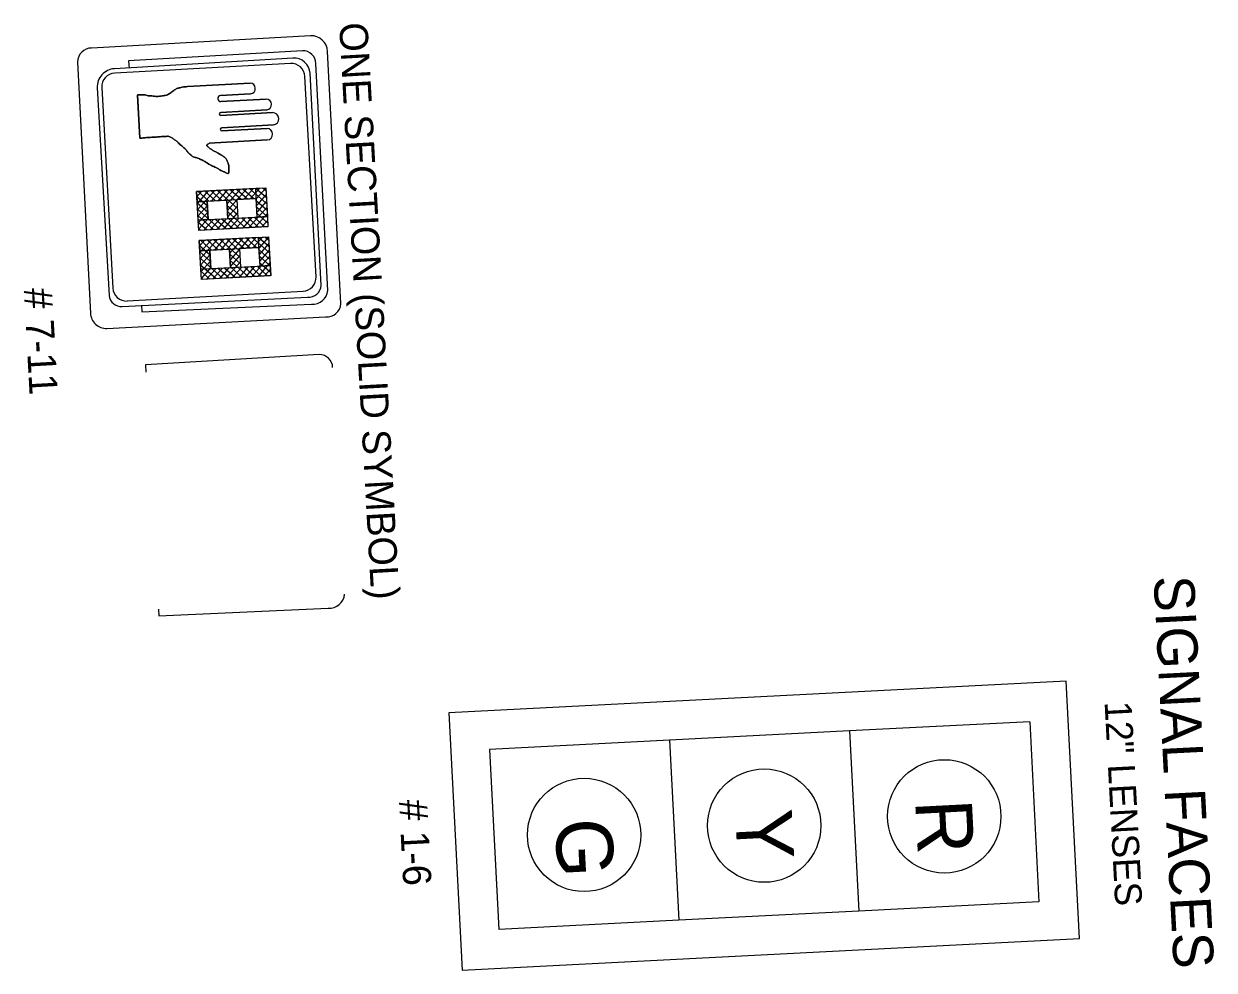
# Model space of a CAD drawing. Extents: x -218554 to 420030, y -566264 to -483460.
# Drawn here: x -218285.8 to -218207.2, y -484168.8 to -484106.3 of the extents above; entities that cross this region are included whole.
import ezdxf

# ---------------------------------------------------------------- set-up
doc = ezdxf.new("R2010")
doc.units = 0
for name, color, linetype in [('G-ANNO-STMP', 7, 'Continuous'), ('Level 1', 7, 'Continuous'), ('Level 61', 7, 'Continuous')]:
    doc.layers.add(name, color=color, linetype=linetype)

msp = doc.modelspace()

# ---------------------------------------------------------------- linework, layer by layer
at = {"layer": 'Level 1'}
for p, q in [((-218266.858, -484107.089), (-218281.297, -484107.896)), ((-218264.85, -484124.763), (-218265.721, -484108.12)), ((-218282.226, -484108.821), (-218281.371, -484125.397)), ((-218268.029, -484108.558), (-218279.793, -484109.264)), ((-218265.704, -484123.89), (-218266.495, -484108.923)), ((-218266.149, -484123.569), (-218266.874, -484109.566)), ((-218280.924, -484110.527), (-218280.144, -484124.236)), ((-218274.981, -484110.441), (-218270.845, -484110.213)), ((-218270.845, -484110.213), (-218274.981, -484110.441)), ((-218278.123, -484113.841), (-218278.279, -484111.01)), ((-218278.264, -484110.994), (-218278.124, -484113.853)), ((-218270.814, -484110.923), (-218272.786, -484111.031)), ((-218272.786, -484111.031), (-218270.814, -484110.923)), ((-218272.764, -484111.431), (-218269.772, -484111.266)), ((-218269.772, -484111.266), (-218272.764, -484111.431)), ((-218272.779, -484112.349), (-218269.354, -484112.16)), ((-218269.354, -484112.16), (-218272.779, -484112.349)), ((-218269.741, -484111.977), (-218272.775, -484112.144)), ((-218272.775, -484112.144), (-218269.741, -484111.977)), ((-218272.707, -484113.367), (-218269.722, -484113.203)), ((-218269.722, -484113.203), (-218272.707, -484113.367)), ((-218269.301, -484112.975), (-218272.702, -484113.162)), ((-218272.702, -484113.162), (-218269.301, -484112.975)), ((-218278.126, -484113.855), (-218278.123, -484113.841)), ((-218269.705, -484113.964), (-218273.547, -484114.175)), ((-218273.547, -484114.175), (-218269.705, -484113.964)), ((-218271.049, -484117.19), (-218272.344, -484118.636)), ((-218270.624, -484117.167), (-218271.253, -484117.869)), ((-218270.863, -484117.18), (-218269.742, -484118.184)), ((-218270.2, -484117.144), (-218270.829, -484117.846)), ((-218270.438, -484117.157), (-218269.766, -484117.759)), ((-218269.799, -484117.147), (-218270.428, -484117.85)), ((-218270.014, -484117.133), (-218269.789, -484117.335)), ((-218274.355, -484117.686), (-218273.652, -484118.315)), ((-218274.021, -484117.354), (-218274.352, -484117.724)), ((-218273.596, -484117.331), (-218274.329, -484118.149)), ((-218273.172, -484117.307), (-218274.306, -484118.573)), ((-218274.259, -484117.367), (-218273.557, -484117.996)), ((-218273.835, -484117.344), (-218273.133, -484117.973)), ((-218273.41, -484117.32), (-218272.708, -484117.949)), ((-218272.747, -484117.284), (-218273.376, -484117.986)), ((-218272.986, -484117.297), (-218271.686, -484118.462)), ((-218272.323, -484117.261), (-218272.952, -484117.963)), ((-218272.561, -484117.274), (-218271.709, -484118.037)), ((-218271.898, -484117.237), (-218272.527, -484117.94)), ((-218272.382, -484117.932), (-218272.315, -484119.162)), ((-218271.473, -484117.214), (-218272.367, -484118.212)), ((-218272.137, -484117.25), (-218271.434, -484117.879)), ((-218271.717, -484117.895), (-218271.649, -484119.125)), ((-218271.712, -484117.227), (-218271.01, -484117.856)), ((-218271.287, -484117.204), (-218270.585, -484117.833)), ((-218270.421, -484117.979), (-218269.719, -484118.608)), ((-218269.776, -484117.572), (-218270.405, -484118.274)), ((-218274.331, -484118.11), (-218273.629, -484118.739)), ((-218274.308, -484118.535), (-218272.831, -484119.858)), ((-218273.653, -484118.296), (-218274.282, -484118.998)), ((-218273.63, -484118.72), (-218274.259, -484119.423)), ((-218272.365, -484118.257), (-218271.662, -484118.886)), ((-218272.341, -484118.682), (-218271.132, -484119.764)), ((-218271.691, -484118.358), (-218272.32, -484119.061)), ((-218269.729, -484118.421), (-218270.922, -484119.752)), ((-218270.398, -484118.404), (-218269.696, -484119.033)), ((-218269.753, -484117.996), (-218270.382, -484118.699)), ((-218274.284, -484118.959), (-218273.255, -484119.881)), ((-218274.261, -484119.384), (-218273.68, -484119.904)), ((-218273.606, -484119.145), (-218274.235, -484119.847)), ((-218273.265, -484119.214), (-218273.894, -484119.916)), ((-218272.84, -484119.19), (-218273.469, -484119.893)), ((-218273.109, -484119.205), (-218272.406, -484119.834)), ((-218272.416, -484119.167), (-218273.045, -484119.869)), ((-218272.684, -484119.182), (-218271.982, -484119.811)), ((-218271.668, -484118.783), (-218272.62, -484119.846)), ((-218272.318, -484119.106), (-218271.557, -484119.787)), ((-218271.566, -484119.12), (-218272.195, -484119.823)), ((-218271.142, -484119.097), (-218271.771, -484119.799)), ((-218271.41, -484119.112), (-218270.708, -484119.741)), ((-218270.717, -484119.074), (-218271.346, -484119.776)), ((-218270.986, -484119.088), (-218270.283, -484119.717)), ((-218270.561, -484119.065), (-218269.859, -484119.694)), ((-218269.706, -484118.846), (-218270.497, -484119.729)), ((-218270.375, -484118.828), (-218269.672, -484119.457)), ((-218269.683, -484119.27), (-218270.073, -484119.706)), ((-218274.238, -484119.809), (-218274.104, -484119.928)), ((-218274.176, -484120.923), (-218273.474, -484121.552)), ((-218273.843, -484120.591), (-218274.174, -484120.962)), ((-218273.418, -484120.568), (-218274.151, -484121.386)), ((-218272.993, -484120.545), (-218274.127, -484121.811)), ((-218274.081, -484120.605), (-218273.379, -484121.234)), ((-218273.657, -484120.581), (-218272.954, -484121.21)), ((-218273.232, -484120.558), (-218272.53, -484121.187)), ((-218272.569, -484120.521), (-218273.198, -484121.224)), ((-218272.807, -484120.534), (-218271.507, -484121.699)), ((-218272.144, -484120.498), (-218272.773, -484121.2)), ((-218272.383, -484120.511), (-218271.531, -484121.274)), ((-218271.72, -484120.475), (-218272.349, -484121.177)), ((-218271.295, -484120.451), (-218272.189, -484121.449)), ((-218270.871, -484120.428), (-218272.165, -484121.873)), ((-218271.958, -484120.488), (-218271.256, -484121.117)), ((-218271.534, -484120.464), (-218270.831, -484121.093)), ((-218271.109, -484120.441), (-218270.407, -484121.07)), ((-218270.446, -484120.404), (-218271.075, -484121.107)), ((-218270.685, -484120.418), (-218269.564, -484121.421)), ((-218270.022, -484120.381), (-218270.651, -484121.083)), ((-218270.26, -484120.394), (-218269.587, -484120.997)), ((-218269.621, -484120.385), (-218270.25, -484121.087)), ((-218269.598, -484120.809), (-218270.227, -484121.511)), ((-218269.835, -484120.371), (-218269.611, -484120.572)), ((-218274.153, -484121.348), (-218273.451, -484121.977)), ((-218274.129, -484121.772), (-218272.652, -484123.095)), ((-218273.475, -484121.533), (-218274.104, -484122.235)), ((-218272.204, -484121.169), (-218272.136, -484122.399)), ((-218272.186, -484121.494), (-218271.484, -484122.123)), ((-218271.513, -484121.596), (-218272.142, -484122.298)), ((-218271.538, -484121.132), (-218271.471, -484122.362)), ((-218269.551, -484121.658), (-218270.743, -484122.99)), ((-218270.243, -484121.217), (-218269.541, -484121.846)), ((-218270.22, -484121.641), (-218269.517, -484122.27)), ((-218269.574, -484121.234), (-218270.203, -484121.936)), ((-218274.106, -484122.197), (-218273.077, -484123.118)), ((-218274.083, -484122.621), (-218273.502, -484123.142)), ((-218273.452, -484121.958), (-218274.081, -484122.66)), ((-218273.428, -484122.382), (-218274.057, -484123.084)), ((-218273.086, -484122.451), (-218273.715, -484123.153)), ((-218272.662, -484122.428), (-218273.291, -484123.13)), ((-218272.93, -484122.443), (-218272.228, -484123.072)), ((-218272.237, -484122.404), (-218272.866, -484123.107)), ((-218272.506, -484122.419), (-218271.803, -484123.048)), ((-218271.49, -484122.02), (-218272.442, -484123.083)), ((-218272.163, -484121.919), (-218270.954, -484123.001)), ((-218272.139, -484122.343), (-218271.379, -484123.025)), ((-218271.388, -484122.358), (-218272.017, -484123.06)), ((-218270.964, -484122.334), (-218271.593, -484123.037)), ((-218271.232, -484122.349), (-218270.53, -484122.978)), ((-218270.539, -484122.311), (-218271.168, -484123.013)), ((-218270.807, -484122.326), (-218270.105, -484122.955)), ((-218270.383, -484122.302), (-218269.681, -484122.931)), ((-218269.528, -484122.083), (-218270.319, -484122.966)), ((-218270.196, -484122.066), (-218269.494, -484122.695)), ((-218269.504, -484122.507), (-218269.894, -484122.943)), ((-218274.059, -484123.046), (-218273.926, -484123.165)), ((-218279.286, -484124.948), (-218267.051, -484124.332)), ((-218280.29, -484126.408), (-218265.861, -484125.648))]:
    msp.add_line(p, q, dxfattribs=at)
for points in [[(-218267.382, -484108.074), (-218278.854, -484108.74), (-218278.828, -484109.222)], [(-218268.174, -484108.914), (-218279.777, -484109.553)], [(-218266.488, -484122.997), (-218267.216, -484109.772)], [(-218280.635, -484110.511), (-218279.907, -484123.736)], [(-218272.315, -484119.162), (-218273.602, -484119.232), (-218273.669, -484118.002), (-218272.382, -484117.932)], [(-218271.649, -484119.125), (-218270.362, -484119.054), (-218270.43, -484117.824), (-218271.717, -484117.895)], [(-218271.471, -484122.362), (-218270.184, -484122.291), (-218270.252, -484121.061), (-218271.538, -484121.132)], [(-218272.136, -484122.399), (-218273.423, -484122.47), (-218273.491, -484121.24), (-218272.204, -484121.169)], [(-218278.949, -484124.593), (-218267.345, -484123.954)], [(-218277.999, -484124.874), (-218277.975, -484125.308), (-218266.795, -484124.802)], [(-218266.278, -484128.135), (-218277.749, -484128.801), (-218277.723, -484129.283)], [(-218276.895, -484144.935), (-218276.87, -484145.369), (-218265.69, -484144.863)]]:
    msp.add_lwpolyline(points, dxfattribs=at)
for points in [[(-218269.801, -484117.122), (-218269.66, -484119.683), (-218274.231, -484119.935), (-218274.372, -484117.373)], [(-218274.372, -484117.373), (-218274.337, -484118.029), (-218270.43, -484117.824), (-218270.464, -484117.169)], [(-218269.801, -484117.122), (-218269.701, -484119.019), (-218270.362, -484119.054), (-218270.461, -484117.156)], [(-218271.717, -484117.895), (-218271.652, -484119.127), (-218272.315, -484119.162), (-218272.379, -484117.93)], [(-218273.669, -484118.002), (-218273.605, -484119.224), (-218274.266, -484119.258), (-218274.33, -484118.037)], [(-218269.701, -484119.019), (-218269.666, -484119.696), (-218274.231, -484119.935), (-218274.266, -484119.258)], [(-218269.623, -484120.359), (-218269.481, -484122.92), (-218274.052, -484123.172), (-218274.193, -484120.611)], [(-218274.193, -484120.611), (-218274.159, -484121.266), (-218270.252, -484121.061), (-218270.286, -484120.406)], [(-218269.623, -484120.359), (-218269.523, -484122.257), (-218270.184, -484122.291), (-218270.283, -484120.394)], [(-218273.491, -484121.24), (-218273.427, -484122.461), (-218274.088, -484122.496), (-218274.152, -484121.274)], [(-218271.538, -484121.132), (-218271.474, -484122.364), (-218272.136, -484122.399), (-218272.201, -484121.167)], [(-218269.523, -484122.257), (-218269.488, -484122.933), (-218274.052, -484123.172), (-218274.088, -484122.496)]]:
    msp.add_lwpolyline(points, close=True, dxfattribs=at)
for centre, radius, start, end in [((-218266.806, -484108.173), 1.086, 2.77432, 92.77432), ((-218281.298, -484108.823), 0.927, 89.93321, 179.93321), ((-218267.363, -484108.942), 0.869, 1.27514, 91.27514), ((-218279.727, -484110.461), 1.198, 93.15216, 183.15216), ((-218268.124, -484109.822), 0.909, 3.15216, 93.15216), ((-218267.955, -484109.639), 1.083, 3.88192, 93.88192), ((-218279.727, -484110.461), 0.909, 93.15216, 183.15216), ((-218270.85, -484110.568), 0.356, 275.81971, 89.16653), ((-218270.85, -484110.568), 0.356, 275.81971, 89.16653), ((-218272.776, -484111.231), 0.2, 93.15216, 273.15216), ((-218272.776, -484111.231), 0.2, 93.15216, 273.15216), ((-218269.777, -484111.622), 0.356, 275.81971, 89.16653), ((-218269.777, -484111.622), 0.356, 275.81971, 89.16653), ((-218272.777, -484112.246), 0.102, 88.57477, 268.57477), ((-218272.777, -484112.246), 0.102, 88.57477, 268.57477), ((-218269.351, -484112.569), 0.409, 277.05213, 90.39894), ((-218269.351, -484112.569), 0.409, 277.05213, 90.39894), ((-218272.704, -484113.263), 0.104, 88.04746, 268.04746), ((-218272.704, -484113.263), 0.104, 88.04746, 268.04746), ((-218269.736, -484113.584), 0.381, 274.62974, 87.97656), ((-218269.736, -484113.584), 0.381, 274.62974, 87.97656), ((-218267.396, -484123.047), 0.909, 273.15216, 3.15216), ((-218279.359, -484124.163), 0.788, 185.26181, 275.26181), ((-218278.999, -484123.686), 0.909, 183.15216, 273.15216), ((-218266.982, -484123.499), 0.836, 265.22621, 355.22621), ((-218266.706, -484123.8), 1.005, 264.91062, 354.91062), ((-218265.798, -484124.7), 0.95, 266.18024, 356.18024), ((-218280.324, -484125.362), 1.047, 181.91264, 271.91264), ((-218266.259, -484129.003), 0.869, 1.27514, 91.27514), ((-218265.601, -484143.861), 1.005, 264.91062, 354.91062)]:
    msp.add_arc(centre, radius, start, end, dxfattribs=at)
for points in [[(-218278.264, -484110.994), (-218278.107, -484110.985), (-218277.841, -484110.981), (-218277.562, -484111.044), (-218277.246, -484111.066), (-218277.068, -484111.086), (-218276.724, -484111.067), (-218276.441, -484111.022), (-218276.296, -484110.984), (-218276.057, -484110.823), (-218275.821, -484110.653), (-218275.62, -484110.553), (-218275.406, -484110.502), (-218275.241, -484110.464), (-218275.134, -484110.458), (-218274.981, -484110.441)], [(-218274.981, -484110.441), (-218275.134, -484110.458), (-218275.241, -484110.464), (-218275.406, -484110.502), (-218275.62, -484110.553), (-218275.821, -484110.653), (-218276.057, -484110.823), (-218276.296, -484110.984), (-218276.441, -484111.022), (-218276.724, -484111.067), (-218277.068, -484111.086), (-218277.246, -484111.066), (-218277.562, -484111.044), (-218277.841, -484110.981), (-218278.107, -484110.985), (-218278.264, -484110.994)], [(-218273.546, -484114.173), (-218273.55, -484114.202), (-218273.627, -484114.245), (-218273.684, -484114.297), (-218273.691, -484114.327), (-218273.68, -484114.376), (-218273.638, -484114.403), (-218273.535, -484114.487), (-218273.453, -484114.55), (-218273.392, -484114.586), (-218273.341, -484114.623), (-218273.249, -484114.688), (-218273.168, -484114.721), (-218273.057, -484114.775), (-218272.996, -484114.81), (-218272.884, -484114.873), (-218272.781, -484114.946), (-218272.68, -484115), (-218272.578, -484115.063), (-218272.506, -484115.118), (-218272.423, -484115.202), (-218272.377, -484115.308), (-218272.344, -484115.365), (-218272.311, -484115.452), (-218272.277, -484115.528), (-218272.25, -484115.646), (-218272.245, -484115.744), (-218272.238, -484115.871), (-218272.241, -484115.989), (-218272.253, -484116.127), (-218272.271, -484116.168), (-218272.299, -484116.179), (-218272.43, -484116.127), (-218272.501, -484116.092), (-218272.573, -484116.057), (-218272.653, -484116.022), (-218272.703, -484116.005), (-218272.835, -484115.933), (-218273.019, -484115.825), (-218273.312, -484115.683), (-218273.646, -484115.505), (-218273.881, -484115.361), (-218274.033, -484115.28), (-218274.174, -484115.21), (-218274.287, -484115.171), (-218274.344, -484115.15), (-218274.586, -484115.076), (-218274.76, -484114.947), (-218274.884, -484114.846), (-218275.01, -484114.695), (-218275.085, -484114.601), (-218275.354, -484114.36), (-218275.581, -484114.146), (-218275.737, -484114.007), (-218275.91, -484113.889), (-218275.987, -484113.83), (-218276.095, -484113.781), (-218276.195, -484113.728), (-218276.412, -484113.74), (-218276.606, -484113.74), (-218276.783, -484113.75), (-218277.018, -484113.773), (-218277.244, -484113.786), (-218277.607, -484113.806), (-218277.9, -484113.831), (-218278.007, -484113.846), (-218278.086, -484113.851), (-218278.124, -484113.853)], [(-218278.124, -484113.853), (-218278.086, -484113.851), (-218278.007, -484113.846), (-218277.9, -484113.831), (-218277.607, -484113.806), (-218277.244, -484113.786), (-218277.018, -484113.773), (-218276.783, -484113.75), (-218276.606, -484113.74), (-218276.412, -484113.74), (-218276.195, -484113.728), (-218276.095, -484113.781), (-218275.987, -484113.83), (-218275.91, -484113.889), (-218275.737, -484114.007), (-218275.581, -484114.146), (-218275.354, -484114.36), (-218275.085, -484114.601), (-218275.01, -484114.695), (-218274.884, -484114.846), (-218274.76, -484114.947), (-218274.586, -484115.076), (-218274.344, -484115.15), (-218274.287, -484115.171), (-218274.174, -484115.21), (-218274.033, -484115.28), (-218273.881, -484115.361), (-218273.646, -484115.505), (-218273.312, -484115.683), (-218273.019, -484115.825), (-218272.835, -484115.933), (-218272.703, -484116.005), (-218272.653, -484116.022), (-218272.573, -484116.057), (-218272.501, -484116.092), (-218272.43, -484116.127), (-218272.299, -484116.179), (-218272.271, -484116.168), (-218272.253, -484116.127), (-218272.241, -484115.989), (-218272.238, -484115.871), (-218272.245, -484115.744), (-218272.25, -484115.646), (-218272.277, -484115.528), (-218272.311, -484115.452), (-218272.344, -484115.365), (-218272.377, -484115.308), (-218272.423, -484115.202), (-218272.506, -484115.118), (-218272.578, -484115.063), (-218272.68, -484115), (-218272.781, -484114.946), (-218272.884, -484114.873), (-218272.996, -484114.81), (-218273.057, -484114.775), (-218273.168, -484114.721), (-218273.249, -484114.688), (-218273.341, -484114.623), (-218273.392, -484114.586), (-218273.453, -484114.55), (-218273.535, -484114.487), (-218273.638, -484114.403), (-218273.68, -484114.376), (-218273.691, -484114.327), (-218273.684, -484114.297), (-218273.627, -484114.245), (-218273.55, -484114.202), (-218273.546, -484114.173)]]:
    msp.add_spline(points, degree=3, dxfattribs=at)
at = {"layer": 'Level 61'}
for p, q in [((-218219.388, -484152.359), (-218231.273, -484152.972)), ((-218219.388, -484152.359), (-218218.775, -484164.243)), ((-218231.273, -484152.972), (-218243.158, -484153.585)), ((-218231.273, -484152.972), (-218230.66, -484164.857)), ((-218243.158, -484153.585), (-218255.043, -484154.198)), ((-218243.158, -484153.585), (-218242.545, -484165.47)), ((-218255.043, -484154.198), (-218254.43, -484166.083)), ((-218218.775, -484164.243), (-218230.66, -484164.857)), ((-218230.66, -484164.857), (-218242.545, -484165.47)), ((-218242.545, -484165.47), (-218254.43, -484166.083))]:
    msp.add_line(p, q, dxfattribs=at)
msp.add_lwpolyline([(-218256.845, -484168.761), (-218216.097, -484166.659), (-218216.973, -484149.68), (-218257.721, -484151.783)], close=True, dxfattribs=at)
for centre in [(-218225.024, -484158.608), (-218236.909, -484159.221), (-218248.794, -484159.834)]:
    msp.add_circle(centre, 3.74, dxfattribs=at)

# ---------------------------------------------------------------- texts
at = {"layer": 'G-ANNO-STMP'}
for s, height, rotation, p in [('ONE SECTION (SOLID SYMBOL)', 1.86667, 273.19877, (-218264.965, -484106.257)), ('# 7-11', 1.8667, 273.19877, (-218285.782, -484123.777)), ('# 1-6', 1.8667, 272.95326, (-218261.016, -484157.549))]:
    msp.add_text(s, height=height, rotation=rotation, dxfattribs=at).set_placement(p)
at = {"layer": 'Level 61'}
for s, height, rotation, p in [('SIGNAL FACES', 2.66667, 272.95326, (-218211.212, -484142.781)), ('12" LENSES', 1.7778, 273.02529, (-218214.447, -484151.051)), ('R', 3.739, 272.95326, (-218226.95, -484157.574)), ('Y', 3.739, 272.95326, (-218238.832, -484158.231)), ('G', 3.739, 272.95326, (-218250.718, -484158.833))]:
    msp.add_text(s, height=height, rotation=rotation, dxfattribs=at).set_placement(p)

doc.saveas('drawing.dxf')
